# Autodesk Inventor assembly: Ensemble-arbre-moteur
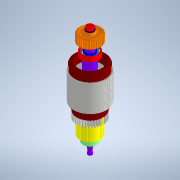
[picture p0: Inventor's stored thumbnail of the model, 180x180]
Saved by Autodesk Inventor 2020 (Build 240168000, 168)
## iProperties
Created: 2020-09
Part Number: Ensemble-arbre-moteur
Document SubType Name: Assembly
Designer: Bruno
Author: Bruno
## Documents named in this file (7)
- D:\Téléchargements-2016-17\scoot_elec\Ensemble-arbre-moteur.iam
- D:\Téléchargements-2016-17\scoot_elec\pièces à assembler\Arbre moteur.ipt
- D:\Téléchargements-2016-17\scoot_elec\pièces à assembler\Poulie crantée motrice.ipt
- D:\Téléchargements-2016-17\scoot_elec\pièces à assembler\Vis HM10-20.ipt
- D:\Téléchargements-2016-17\scoot_elec\pièces à assembler\Rondelle plate M10.ipt
- D:\Téléchargements-2016-17\scoot_elec\pièces à assembler\ROULEMENT 6004-D12\Roulement 6004-2RS.iam
- D:\Téléchargements-2016-17\scoot_elec\pièces à assembler\ROULEMENT 6202\Roulement 6202.iam
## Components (6 placed, 6 different names)
1. Arbre moteur:1 — Placage:1, Affleurement:1, Logement:3, Logement:4
2. Poulie crantée motrice:1 — Placage:1, Affleurement:1, Logement:1
3. Vis HM10-20:1 — Logement:2
4. Rondelle plate M10:1 — Logement:1, Logement:2
5. Roulement 6004-2RS:1 [sub-assembly] — Logement:3
6. Roulement 6202:1 [sub-assembly] — Logement:4
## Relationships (6: Insert 4, Mate 1, Flush 1)
- Placage:1 [Mate]: Arbre moteur:1 ↔ Poulie crantée motrice:1
- Affleurement:1 [Flush]: Arbre moteur:1 ↔ Poulie crantée motrice:1
- Logement:1 [Insert]: Poulie crantée motrice:1 ↔ Rondelle plate M10:1
- Logement:2 [Insert]: Vis HM10-20:1 ↔ Rondelle plate M10:1
- Logement:3 [Insert]: Arbre moteur:1 ↔ Roulement 6004-2RS:1
- Logement:4 [Insert]: Arbre moteur:1 ↔ Roulement 6202:1
